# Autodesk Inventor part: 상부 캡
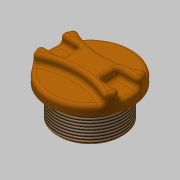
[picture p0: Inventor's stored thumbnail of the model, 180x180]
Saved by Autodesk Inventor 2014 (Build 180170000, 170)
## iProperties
Created: 2016-09
Part Number: 상부 캡
Material: PC/ABS 플라스틱
Document SubType Name: Modeling
Designer: mduedu
Density: 1.493 g/cm^3
Appearance: Orange
Mass: 32.6937 g
Surface Area: 67.9046 cm^2
Volume: 21.898 cm^3
Author: mduedu
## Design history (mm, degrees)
sketch "스케치1"
  geometry: C1 r 22.5 at (0, 0); 1 further point
  constraints: 1 centre point, 1 coincident
  dimensions: "d0" = 45 diameter of C1
extrude "돌출1" new body sketch "스케치1" distance "d1" = 10; taper "d2" = 0 deg
sketch "스케치2" dims "d4" = 80
  geometry: C1 r 22.5 at (0, 0) reference; 3 further points
  constraints: 3 vertical alignment, 2 other
  dimensions: "d3" = 7 distance of point (0, 7) point (0, 0)
extrude "돌출2" cut sketch "스케치2" distance "d5" = 5; taper "d6" = 0 deg
sketch "스케치3"
  geometry: L1 (-22.5, 0)-(0, 0); L2 (-21.937, 5)-(-10, 5); L3 (-10, 5)-(-10, -5); L4 (-10, -5)-(-21.937, -5); A1 r 22.5 centre (0, 0) between (-19.118, 11.864) and (-19.118, -11.864) reference; A2 r 22.5 centre (0, 0) between (-21.937, 5) and (-21.937, -5); 1 further point
  constraints: 8 end point, 5 point on circle, 2 horizontal, 1 centre point, 1 coincident, 1 parallel, 1 perpendicular, 1 symmetric about line
  dimensions: "d7" = 10 distance from line of L3 point (0, 0); "d8" = 10 distance of L2.end L3.end
extrude "돌출3" cut sketch "스케치3" distance "d9" = 5; taper "d10" = 0 deg
fillet "모깎기1" dims "d11" = 2
fillet "모깎기2" dims "d12" = 2
fillet "모깎기3" dims "d13" = 2
sketch "스케치4"
  geometry: C1 r 17.5 at (0, 0); 1 further point
  constraints: 1 centre point, 1 coincident
  dimensions: "d14" = 35 diameter of C1
extrude "돌출4" join sketch "스케치4" distance "d15" = 17; taper "d16" = 0 deg
sketch "스케치5"
  geometry: C1 r 12.5 at (0, 0); 1 further point
  constraints: 1 centre point, 1 coincident
  dimensions: "d17" = 25 diameter of C1
extrude "돌출5" cut sketch "스케치5" distance "d18" = 10; taper "d19" = 0 deg
fillet "모깎기4" dims "d20" = 3
feature "스레드1" dims "d21" = 10, "d22" = 0
chamfer "모따기1" distance "d23" = 1; stored, may be unused: second distance "d24" = 2, angle "d25" = 45 deg
node "솔리드1"
mirror "대칭1"
mirror "대칭2"
node "투영된 루프1"
